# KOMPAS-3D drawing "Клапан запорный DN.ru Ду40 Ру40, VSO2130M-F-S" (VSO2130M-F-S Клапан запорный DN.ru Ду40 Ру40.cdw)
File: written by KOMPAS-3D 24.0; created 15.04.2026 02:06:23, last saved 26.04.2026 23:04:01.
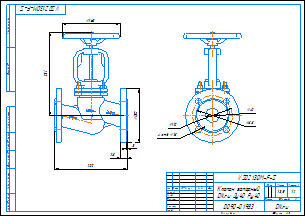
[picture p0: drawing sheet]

Document properties: Автор: DN.ru; Форматы листов документа: A3; Полное имя файла: VSO2130M-F-S Клапан запорный DN.ru Ду40 Ру40.m3d; Масса: 13.5; Наименование: Клапан запорный DN.ru Ду40 Ру40; Количество листов документа: 1; Примечание: D090-01983

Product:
- Part/product: Клапан запорный DN.ru Ду40 Ру40  | designation VSO2130M-F-S
    Масса: 13.5
    Раздел спецификации: Прочие изделия
    Примечание: D090-01983

Views: Вид 1, Вид:1, Проекционный вид 2
Referenced files in C:\Работа\VSO2130M-F-S Клапан запорный DN.ru\DN15\: VSO2130M-F-S DN15 PN40  Клапан запорный сильфонный DN.ru.m3d
Referenced files in C:\Работа\VSO2130M-F-S Клапан запорный DN.ru Ду-x Ру40\DN40\: VSO2130M-F-S Клапан запорный DN.ru Ду40 Ру40.m3d
Referenced files in C:\Program Files\ASCON\KOMPAS-3D v24\Templates\: Чертеж_DN.ru.cdt
Referenced files in C:\Работа\ГОТОВЫЕ ИСХОДНИКИ\VSO2130M-F-S Клапан запорный сальниковый DN.ru Ду15-100 Ру40\DN40\: VSO2130M-F-S Клапан запорный DN.ru Ду40 Ру40.m3d
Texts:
  VSO2130M-F-S
  Чертеж_DN.ru.cdt
  Клапан запорный
  DN.ru Ду40 Ру40
  Клапан запорный DN.ru Ду40 Ру40
  VSO2130M-F-S Клапан запорный DN.ru Ду40 Ру40
Dimensions and other numbers on the sheet: 0; 3; 2; 4; 150; 18; 231; 160; 200; 5; 40; 88; 110; 4 отв.; 1:2; 1; 13,5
